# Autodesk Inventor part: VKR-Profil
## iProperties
Created: 2001-12
Part Number: VKR-Profil
Material: Steel, Mild
Description: VKR 75x75x3_660
Document SubType Name: Modeling
Designer: Tobben
Control State: 0
Master: False
Checked Out: False
Shininess: 64.0
Length Units: 11269
Angle Units: 11279
Time Units: 11290
Mass Units: 11283
Length Display Precision: 3
Angle Display Precision: 2
Density: 0.0
Volumn: 0.0
Area: 0.0
PropertySet Name: Model Information
Author: Tobben
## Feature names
1. Derived Body1 [Tagging]
